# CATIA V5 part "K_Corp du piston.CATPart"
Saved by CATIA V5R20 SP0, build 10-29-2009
Part number: Corp du piston
Property "Diamètre joint": 20 mm
Property "Longueur coprs du piston": 300 mm
Property "Diamètre piston": 100 mm
Property "Epaisseur piston": 5 mm
Bounding box of the stored display mesh (mm): x -49.995 to 49.995, y -49.995 to 49.995, z -69.98 to 320
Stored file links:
  C:\Users\thinkmotion1\Desktop\Khaled_IAO_Pack2\Problemes\IAO_2010_1405_jpalas\IAO_PALAS\Khaled_Palas\K_Corp du piston.CATPart
  C:\Users\Jep\Desktop\ifma\semestre 3\projet IAO\Modelisation catia\Projet IAO.CATProduct
  C:\Users\thinkmotion1\Desktop\Khaled_IAO_Pack2\Problemes\IAO_2010_1405_jpalas\IAO_PALAS\Palas\Piston.CATPart
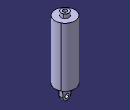
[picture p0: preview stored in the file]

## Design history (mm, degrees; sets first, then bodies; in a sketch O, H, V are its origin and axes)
Body1 (main body)
  Sketch1 on zx-plane, origin (0, 0, 0), H (-1, 0, 0), V (0, 0, 1)
    point P1 (-50, 0)
    line L1 (-50, 0) -> (0, 0)
    line L2 (0, 0) -> (0, 300)
    line L3 (0, 300) -> (0, 300)
    line L4 (0, 300) -> (0, 320)
    line L5 (0, 320) -> (-20, 320)
    line L6 (-20, 320) -> (-20, 300)
    point P7 (-20, 300)
    line L7 (-20, 300) -> (-50, 300)
    line L8 (-50, 300) -> (-50, 0)
    length L1 = 50
    length L5 = 20
    distance L6 L8 = 30
    length L8 = 300
    length L4 = 20
    coincidence: P1 H, P7 L3, L2 V
    horizontal: L1 H, L3 H, L5 H, L7 H
    vertical: L2 V, L4 V, L6 V, L8 V
  Shaft1: profile Sketch1, axis Sketch1.L2, angle 360
  Sketch2 on face of Shaft1 from Sketch1.L5, origin (0, 0, 320), H (1, 0, 0), V (0, 1, 0)
    point P1 (0, 0)
    reference projected circle E1 centre (0, 0) radius 20 from edge [face of Shaft1 from Sketch1.L6 | face of Shaft1 from Sketch1.L5]
    concentricity: P1 E1
  Hole1: placed by Sketch2, at (0, 0, 320) direction (0, 0, -1), diameter 20, depth 20
  Sketch3 on face of Shaft1 from Sketch1.L7, origin (20, 0, 300), H (1, 0, 0), V (0, 1, 0)
    circle A1 centre (-20, 0) radius 45
    point P1 (-20, 0)
    reference projected circle E1 centre (-20, 0) radius 50 from edge [face of Shaft1 from Sketch1.L8 | face of Shaft1 from Sketch1.L7]
    radius A1 = 45
    concentricity: P1 E1
  Pocket1: profile Sketch3, direction (0, 0, -1), length 295, opposite side length -5
  Sketch4 on zx-plane, origin (0, 0, 0), H (0, 0, 1), V (1, 0, 0)
    point P1 (0, 25)
    line L1 (0, 25) -> (0, -25)
    line L2 (0, -25) -> (-51.9522, -19.9045)
    line L3 (0, 25) -> (-51.9522, 19.9045)
    arc A1 centre (-50, 0) radius 20 from (-51.9522, 19.9045) to (-51.9522, -19.9045) ccw
    point P5 (-50, 0)
    radius A1 = 20
    length L1 = 50
    distance P5 L1 = 50
    distance P1 H = 25
    coincidence: P1 V, P5 H
    vertical: L1 V
    tangency: L2 A1, A1 L3
  Pad1: profile Sketch4, direction (0, 1, 0), length 10, mirrored extent
  Sketch5 on end face of Pad1, origin (0.0009, 10, -96.4408), H (1, 0, 0), V (0, 0, -1)
    point P1 (-0.0009, -46.4408)
    reference projected arc E1 centre (-0.0009, -46.4408) radius 20 from (19.7841, -43.516) to (-19.7859, -43.516) ccw from edge [face of Pad1 from Sketch4.A1 | end face of Pad1]
    concentricity: P1 E1
  Hole2: placed by Sketch5, at (0, 10, -50) direction (0, -1, 0), diameter 20, through (limit type 3)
